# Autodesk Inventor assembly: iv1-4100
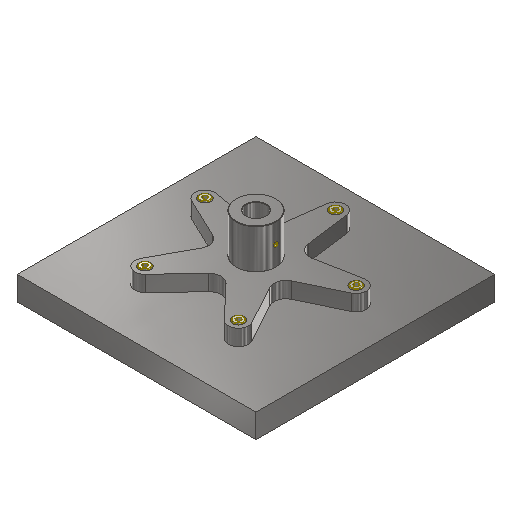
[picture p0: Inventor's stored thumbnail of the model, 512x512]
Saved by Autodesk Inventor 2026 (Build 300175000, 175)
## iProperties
Created: 2022-01
Part Number: iv1-4100
Document SubType Name: Assembly
Designer: Lars Bertram Pedersen
Mass: 32481.2 g
Surface Area: 2971.21 cm^2
Volume: 3096.4 cm^3
Density: 10.49 g/cm^3
Author: Lars Bertram Pedersen
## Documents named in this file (6)
- C:\INV GR\INV GR Assembly\iv1-4100.iam
- C:\INV GR\INV GR Part\iv1-3800.ipt
- C:\INV GR\INV GR Part\iv1-3700.ipt
- C:\INV GR\INV GR Part\iv1-3900.ipt
- C:\INV GR\INV GR Assembly\DIN 916 - M6  x  12.ipt
- C:\INV GR\INV GR Assembly\DIN 912 - M8 x 1,25 x 25 x 21,875.ipt
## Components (9 placed, 5 different names)
1. iv1-3800:1 — Mate:1, Mate:2, Mate:3, Angle:1
2. iv1-3700:1 — Mate:1, Mate:2, Mate:3, Mate:4, Mate:5
3. DIN 912 - M8 x 1,25 x 25 x 21,875:1
4. DIN 912 - M8 x 1,25 x 25 x 21,875:2
5. DIN 912 - M8 x 1,25 x 25 x 21,875:3
6. DIN 912 - M8 x 1,25 x 25 x 21,875:4
7. DIN 912 - M8 x 1,25 x 25 x 21,875:5
8. iv1-3900:1 — Mate:4, Mate:5, Angle:1
9. DIN 916 - M6  x  12:1
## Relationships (6: Mate 5, Angle 1)
- Mate:1: iv1-3800:1 ↔ iv1-3700:1
- Mate:2: iv1-3800:1 ↔ iv1-3700:1
- Mate:3: iv1-3800:1 ↔ iv1-3700:1
- Mate:4: iv1-3700:1 ↔ iv1-3900:1
- Mate:5: iv1-3700:1 ↔ iv1-3900:1
- Angle:1: iv1-3800:1 ↔ iv1-3900:1
